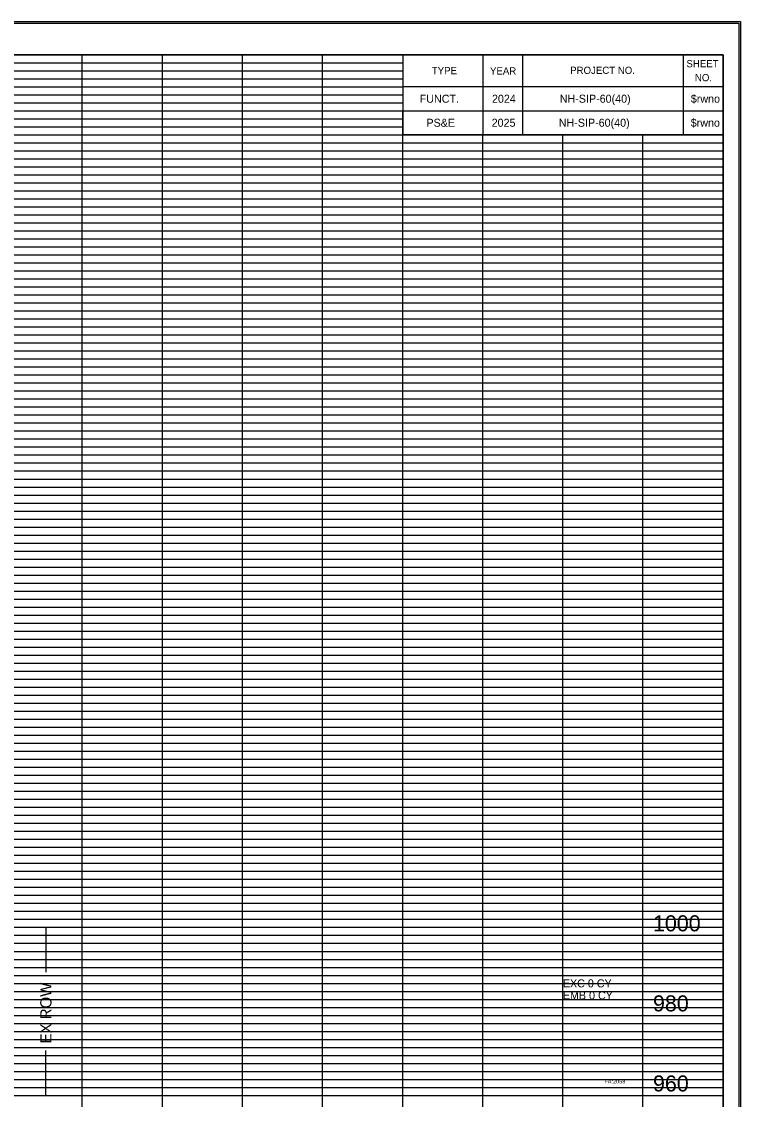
# Model space of a CAD drawing. Extents: x 2313580 to 2322968, y 282099 to 303247.
# Drawn here: x 2315763.7 to 2315943.2, y 287746.7 to 288016 of the extents above; entities that cross this region are included whole.
import ezdxf

# ---------------------------------------------------------------- set-up
doc = ezdxf.new("R2010")
doc.units = 0
for name, color, linetype in [('DESIGN - EARTHWORK - Excavation Limit Lines', 7, 'Continuous'), ('DESIGN - SCRATCH - User 1', 7, 'Continuous'), ('DESIGN - SHEET - Corner Text', 7, 'Continuous'), ('DESIGN - SHEET - Light Grid', 7, 'Continuous'), ('DESIGN - SHEET - Linework', 7, 'Continuous'), ('DESIGN - SHEET - Plot Shape', 7, 'Continuous'), ('DESIGN - TYPICAL - Text', 7, 'Continuous'), ('Prop_ CL text', 7, 'Continuous'), ('SURVEY - PROPERTY - ROW Lines Text', 7, 'Continuous')]:
    doc.layers.add(name, color=color, linetype=linetype)

msp = doc.modelspace()

# ---------------------------------------------------------------- linework, layer by layer
at = {"layer": 'DESIGN - SCRATCH - User 1'}
for p, q in [((2315868.88, 287996.67), (2315868.88, 287996.67)), ((2315883.68, 287996.67), (2315883.68, 287996.67)), ((2315908.68, 287996.67), (2315908.68, 287996.67)), ((2315933.68, 287996.67), (2315933.68, 287996.67)), ((2315868.88, 287990.67), (2315868.88, 287990.67)), ((2315883.68, 287990.67), (2315883.68, 287990.67)), ((2315908.68, 287990.67), (2315908.68, 287990.67)), ((2315933.68, 287990.67), (2315933.68, 287990.67))]:
    msp.add_line(p, q, dxfattribs=at)
at = {"layer": 'DESIGN - SHEET - Light Grid'}
for p, q in [((2315618.88, 288005.67), (2315778.88, 288005.67)), ((2315618.88, 288003.67), (2315778.88, 288003.67)), ((2315778.88, 288005.67), (2315858.88, 288005.67)), ((2315778.88, 288003.67), (2315858.88, 288003.67)), ((2315618.88, 288001.67), (2315778.88, 288001.67)), ((2315778.88, 288001.67), (2315858.88, 288001.67)), ((2315618.88, 287999.67), (2315778.88, 287999.67)), ((2315618.88, 287997.67), (2315778.88, 287997.67)), ((2315778.88, 287999.67), (2315858.88, 287999.67)), ((2315778.88, 287997.67), (2315858.88, 287997.67)), ((2315618.88, 287995.67), (2315778.88, 287995.67)), ((2315778.88, 287995.67), (2315858.88, 287995.67)), ((2315618.88, 287993.67), (2315778.88, 287993.67)), ((2315778.88, 287993.67), (2315858.88, 287993.67)), ((2315618.88, 287991.67), (2315778.88, 287991.67)), ((2315618.88, 287989.67), (2315778.88, 287989.67)), ((2315778.88, 287991.67), (2315858.88, 287991.67)), ((2315778.88, 287989.67), (2315858.88, 287989.67)), ((2315618.88, 287985.67), (2315778.88, 287985.67)), ((2315778.88, 287985.67), (2315938.88, 287985.67)), ((2315618.88, 287983.67), (2315778.88, 287983.67)), ((2315618.88, 287981.67), (2315778.88, 287981.67)), ((2315778.88, 287983.67), (2315938.88, 287983.67)), ((2315778.88, 287981.67), (2315938.88, 287981.67)), ((2315618.88, 287979.67), (2315778.88, 287979.67)), ((2315778.88, 287979.67), (2315938.88, 287979.67)), ((2315618.88, 287977.67), (2315778.88, 287977.67)), ((2315778.88, 287977.67), (2315938.88, 287977.67)), ((2315618.88, 287975.67), (2315778.88, 287975.67)), ((2315618.88, 287973.67), (2315778.88, 287973.67)), ((2315778.88, 287975.67), (2315938.88, 287975.67)), ((2315778.88, 287973.67), (2315938.88, 287973.67)), ((2315618.88, 287971.67), (2315778.88, 287971.67)), ((2315778.88, 287971.67), (2315938.88, 287971.67)), ((2315618.88, 287969.67), (2315778.88, 287969.67)), ((2315778.88, 287969.67), (2315938.88, 287969.67)), ((2315618.88, 287965.67), (2315778.88, 287965.67)), ((2315778.88, 287965.67), (2315938.88, 287965.67)), ((2315618.88, 287963.67), (2315778.88, 287963.67)), ((2315778.88, 287963.67), (2315938.88, 287963.67)), ((2315618.88, 287961.67), (2315778.88, 287961.67)), ((2315778.88, 287961.67), (2315938.88, 287961.67)), ((2315618.88, 287959.67), (2315778.88, 287959.67)), ((2315618.88, 287957.67), (2315778.88, 287957.67)), ((2315778.88, 287959.67), (2315938.88, 287959.67)), ((2315778.88, 287957.67), (2315938.88, 287957.67)), ((2315618.88, 287955.67), (2315778.88, 287955.67)), ((2315778.88, 287955.67), (2315938.88, 287955.67)), ((2315618.88, 287953.67), (2315778.88, 287953.67)), ((2315778.88, 287953.67), (2315938.88, 287953.67)), ((2315618.88, 287951.67), (2315778.88, 287951.67)), ((2315618.88, 287949.67), (2315778.88, 287949.67)), ((2315778.88, 287951.67), (2315938.88, 287951.67)), ((2315778.88, 287949.67), (2315938.88, 287949.67)), ((2315618.88, 287945.67), (2315778.88, 287945.67)), ((2315778.88, 287945.67), (2315938.88, 287945.67)), ((2315618.88, 287943.67), (2315778.88, 287943.67)), ((2315618.88, 287941.67), (2315778.88, 287941.67)), ((2315778.88, 287943.67), (2315938.88, 287943.67)), ((2315778.88, 287941.67), (2315938.88, 287941.67)), ((2315618.88, 287939.67), (2315778.88, 287939.67)), ((2315778.88, 287939.67), (2315938.88, 287939.67)), ((2315618.88, 287937.67), (2315778.88, 287937.67)), ((2315778.88, 287937.67), (2315938.88, 287937.67)), ((2315618.88, 287935.67), (2315778.88, 287935.67)), ((2315618.88, 287933.67), (2315778.88, 287933.67)), ((2315778.88, 287935.67), (2315938.88, 287935.67)), ((2315778.88, 287933.67), (2315938.88, 287933.67)), ((2315618.88, 287931.67), (2315778.88, 287931.67)), ((2315778.88, 287931.67), (2315938.88, 287931.67)), ((2315618.88, 287929.67), (2315778.88, 287929.67)), ((2315778.88, 287929.67), (2315938.88, 287929.67)), ((2315618.88, 287925.67), (2315778.88, 287925.67)), ((2315778.88, 287925.67), (2315938.88, 287925.67)), ((2315618.88, 287923.67), (2315778.88, 287923.67)), ((2315778.88, 287923.67), (2315938.88, 287923.67)), ((2315618.88, 287921.67), (2315778.88, 287921.67)), ((2315618.88, 287919.67), (2315778.88, 287919.67)), ((2315778.88, 287921.67), (2315938.88, 287921.67)), ((2315778.88, 287919.67), (2315938.88, 287919.67)), ((2315618.88, 287917.67), (2315778.88, 287917.67)), ((2315778.88, 287917.67), (2315938.88, 287917.67)), ((2315618.88, 287915.67), (2315778.88, 287915.67)), ((2315778.88, 287915.67), (2315938.88, 287915.67)), ((2315618.88, 287913.67), (2315778.88, 287913.67)), ((2315618.88, 287911.67), (2315778.88, 287911.67)), ((2315778.88, 287913.67), (2315938.88, 287913.67)), ((2315778.88, 287911.67), (2315938.88, 287911.67)), ((2315618.88, 287909.67), (2315778.88, 287909.67)), ((2315778.88, 287909.67), (2315938.88, 287909.67)), ((2315618.88, 287905.67), (2315778.88, 287905.67)), ((2315618.88, 287903.67), (2315778.88, 287903.67)), ((2315778.88, 287905.67), (2315938.88, 287905.67)), ((2315778.88, 287903.67), (2315938.88, 287903.67)), ((2315618.88, 287901.67), (2315778.88, 287901.67)), ((2315778.88, 287901.67), (2315938.88, 287901.67)), ((2315618.88, 287899.67), (2315778.88, 287899.67)), ((2315778.88, 287899.67), (2315938.88, 287899.67)), ((2315618.88, 287897.67), (2315778.88, 287897.67)), ((2315618.88, 287895.67), (2315778.88, 287895.67)), ((2315778.88, 287897.67), (2315938.88, 287897.67)), ((2315778.88, 287895.67), (2315938.88, 287895.67)), ((2315618.88, 287893.67), (2315778.88, 287893.67)), ((2315778.88, 287893.67), (2315938.88, 287893.67)), ((2315618.88, 287891.67), (2315778.88, 287891.67)), ((2315778.88, 287891.67), (2315938.88, 287891.67)), ((2315618.88, 287889.67), (2315778.88, 287889.67)), ((2315778.88, 287889.67), (2315938.88, 287889.67)), ((2315618.88, 287885.67), (2315778.88, 287885.67)), ((2315778.88, 287885.67), (2315938.88, 287885.67)), ((2315618.88, 287883.67), (2315778.88, 287883.67)), ((2315778.88, 287883.67), (2315938.88, 287883.67)), ((2315618.88, 287881.67), (2315778.88, 287881.67)), ((2315618.88, 287879.67), (2315778.88, 287879.67)), ((2315778.88, 287881.67), (2315938.88, 287881.67)), ((2315778.88, 287879.67), (2315938.88, 287879.67)), ((2315618.88, 287877.67), (2315778.88, 287877.67)), ((2315778.88, 287877.67), (2315938.88, 287877.67)), ((2315618.88, 287875.67), (2315778.88, 287875.67)), ((2315778.88, 287875.67), (2315938.88, 287875.67)), ((2315618.88, 287873.67), (2315778.88, 287873.67)), ((2315618.88, 287871.67), (2315778.88, 287871.67)), ((2315778.88, 287873.67), (2315938.88, 287873.67)), ((2315778.88, 287871.67), (2315938.88, 287871.67)), ((2315618.88, 287869.67), (2315778.88, 287869.67)), ((2315778.88, 287869.67), (2315938.88, 287869.67)), ((2315618.88, 287865.67), (2315778.88, 287865.67)), ((2315618.88, 287863.67), (2315778.88, 287863.67)), ((2315778.88, 287865.67), (2315938.88, 287865.67)), ((2315778.88, 287863.67), (2315938.88, 287863.67)), ((2315618.88, 287861.67), (2315778.88, 287861.67)), ((2315778.88, 287861.67), (2315938.88, 287861.67)), ((2315618.88, 287859.67), (2315778.88, 287859.67)), ((2315618.88, 287857.67), (2315778.88, 287857.67)), ((2315778.88, 287859.67), (2315938.88, 287859.67)), ((2315778.88, 287857.67), (2315938.88, 287857.67)), ((2315618.88, 287855.67), (2315778.88, 287855.67)), ((2315778.88, 287855.67), (2315938.88, 287855.67)), ((2315618.88, 287853.67), (2315778.88, 287853.67)), ((2315778.88, 287853.67), (2315938.88, 287853.67)), ((2315618.88, 287851.67), (2315778.88, 287851.67)), ((2315618.88, 287849.67), (2315778.88, 287849.67)), ((2315778.88, 287851.67), (2315938.88, 287851.67)), ((2315778.88, 287849.67), (2315938.88, 287849.67)), ((2315618.88, 287845.67), (2315778.88, 287845.67)), ((2315778.88, 287845.67), (2315938.88, 287845.67)), ((2315618.88, 287843.67), (2315778.88, 287843.67)), ((2315618.88, 287841.67), (2315778.88, 287841.67)), ((2315778.88, 287843.67), (2315938.88, 287843.67)), ((2315778.88, 287841.67), (2315938.88, 287841.67)), ((2315618.88, 287839.67), (2315778.88, 287839.67)), ((2315778.88, 287839.67), (2315938.88, 287839.67)), ((2315618.88, 287837.67), (2315778.88, 287837.67)), ((2315778.88, 287837.67), (2315938.88, 287837.67)), ((2315618.88, 287835.67), (2315778.88, 287835.67)), ((2315618.88, 287833.67), (2315778.88, 287833.67)), ((2315778.88, 287835.67), (2315938.88, 287835.67)), ((2315778.88, 287833.67), (2315938.88, 287833.67)), ((2315618.88, 287831.67), (2315778.88, 287831.67)), ((2315778.88, 287831.67), (2315938.88, 287831.67)), ((2315618.88, 287829.67), (2315778.88, 287829.67)), ((2315778.88, 287829.67), (2315938.88, 287829.67)), ((2315618.88, 287825.67), (2315778.88, 287825.67)), ((2315778.88, 287825.67), (2315938.88, 287825.67)), ((2315618.88, 287823.67), (2315778.88, 287823.67)), ((2315778.88, 287823.67), (2315938.88, 287823.67)), ((2315618.88, 287821.67), (2315778.88, 287821.67)), ((2315778.88, 287821.67), (2315938.88, 287821.67)), ((2315618.88, 287819.67), (2315778.88, 287819.67)), ((2315618.88, 287817.67), (2315778.88, 287817.67)), ((2315778.88, 287819.67), (2315938.88, 287819.67)), ((2315778.88, 287817.67), (2315938.88, 287817.67)), ((2315618.88, 287815.67), (2315778.88, 287815.67)), ((2315778.88, 287815.67), (2315938.88, 287815.67)), ((2315618.88, 287813.67), (2315778.88, 287813.67)), ((2315778.88, 287813.67), (2315938.88, 287813.67)), ((2315618.88, 287811.67), (2315778.88, 287811.67)), ((2315618.88, 287809.67), (2315778.88, 287809.67)), ((2315778.88, 287811.67), (2315938.88, 287811.67)), ((2315778.88, 287809.67), (2315938.88, 287809.67)), ((2315618.88, 287805.67), (2315778.88, 287805.67)), ((2315778.88, 287805.67), (2315938.88, 287805.67)), ((2315618.88, 287803.67), (2315778.88, 287803.67)), ((2315618.88, 287801.67), (2315778.88, 287801.67)), ((2315778.88, 287803.67), (2315938.88, 287803.67)), ((2315778.88, 287801.67), (2315938.88, 287801.67)), ((2315618.88, 287799.67), (2315778.88, 287799.67)), ((2315778.88, 287799.67), (2315938.88, 287799.67)), ((2315618.88, 287797.67), (2315778.88, 287797.67)), ((2315778.88, 287797.67), (2315938.88, 287797.67)), ((2315618.88, 287795.67), (2315778.88, 287795.67)), ((2315618.88, 287793.67), (2315778.88, 287793.67)), ((2315778.88, 287795.67), (2315938.88, 287795.67)), ((2315778.88, 287793.67), (2315938.88, 287793.67)), ((2315618.88, 287791.67), (2315778.88, 287791.67)), ((2315778.88, 287791.67), (2315938.88, 287791.67)), ((2315618.88, 287789.67), (2315778.88, 287789.67)), ((2315778.88, 287789.67), (2315938.88, 287789.67)), ((2315618.88, 287785.67), (2315778.88, 287785.67)), ((2315778.88, 287785.67), (2315938.88, 287785.67)), ((2315618.88, 287783.67), (2315778.88, 287783.67)), ((2315778.88, 287783.67), (2315938.88, 287783.67)), ((2315618.88, 287781.67), (2315778.88, 287781.67)), ((2315618.88, 287779.67), (2315778.88, 287779.67)), ((2315778.88, 287781.67), (2315938.88, 287781.67)), ((2315778.88, 287779.67), (2315938.88, 287779.67)), ((2315618.88, 287777.67), (2315778.88, 287777.67)), ((2315778.88, 287777.67), (2315938.88, 287777.67)), ((2315618.88, 287775.67), (2315778.88, 287775.67)), ((2315778.88, 287775.67), (2315938.88, 287775.67)), ((2315618.88, 287773.67), (2315778.88, 287773.67)), ((2315618.88, 287771.67), (2315778.88, 287771.67)), ((2315778.88, 287773.67), (2315938.88, 287773.67)), ((2315778.88, 287771.67), (2315938.88, 287771.67)), ((2315618.88, 287769.67), (2315778.88, 287769.67)), ((2315778.88, 287769.67), (2315938.88, 287769.67)), ((2315618.88, 287765.67), (2315778.88, 287765.67)), ((2315618.88, 287763.67), (2315778.88, 287763.67)), ((2315778.88, 287765.67), (2315938.88, 287765.67)), ((2315778.88, 287763.67), (2315938.88, 287763.67)), ((2315618.88, 287761.67), (2315778.88, 287761.67)), ((2315778.88, 287761.67), (2315938.88, 287761.67)), ((2315618.88, 287759.67), (2315778.88, 287759.67)), ((2315778.88, 287759.67), (2315938.88, 287759.67)), ((2315618.88, 287757.67), (2315778.88, 287757.67)), ((2315618.88, 287755.67), (2315778.88, 287755.67)), ((2315778.88, 287757.67), (2315938.88, 287757.67)), ((2315778.88, 287755.67), (2315938.88, 287755.67)), ((2315618.88, 287753.67), (2315778.88, 287753.67)), ((2315778.88, 287753.67), (2315938.88, 287753.67)), ((2315618.88, 287751.67), (2315778.88, 287751.67)), ((2315778.88, 287751.67), (2315938.88, 287751.67)), ((2315618.88, 287749.67), (2315778.88, 287749.67)), ((2315778.88, 287749.67), (2315938.88, 287749.67))]:
    msp.add_line(p, q, dxfattribs=at)
at = {"layer": 'DESIGN - SHEET - Linework'}
for p, q in [((2315262.42, 288015.95), (2315943.22, 288015.95)), ((2315943.22, 288015.95), (2315943.22, 287579.39)), ((2315778.88, 287587.67), (2315778.88, 288007.67)), ((2315798.88, 287587.67), (2315798.88, 288007.67)), ((2315818.88, 287587.67), (2315818.88, 288007.67)), ((2315838.88, 287587.67), (2315838.88, 288007.67)), ((2315298.88, 287987.67), (2315858.88, 287987.67)), ((2315858.88, 287587.67), (2315858.88, 287987.67)), ((2315878.88, 287587.67), (2315878.88, 287987.67)), ((2315898.88, 287587.67), (2315898.88, 287987.67)), ((2315918.88, 287587.67), (2315918.88, 287987.67)), ((2315298.88, 287967.67), (2315938.88, 287967.67)), ((2315298.88, 287947.67), (2315938.88, 287947.67)), ((2315298.88, 287927.67), (2315938.88, 287927.67)), ((2315298.88, 287907.67), (2315938.88, 287907.67)), ((2315298.88, 287887.67), (2315938.88, 287887.67)), ((2315298.88, 287867.67), (2315938.88, 287867.67)), ((2315298.88, 287847.67), (2315938.88, 287847.67)), ((2315298.88, 287827.67), (2315938.88, 287827.67)), ((2315298.88, 287807.67), (2315938.88, 287807.67)), ((2315298.88, 287787.67), (2315938.88, 287787.67)), ((2315298.88, 287767.67), (2315938.88, 287767.67)), ((2315298.88, 287747.67), (2315938.88, 287747.67))]:
    msp.add_line(p, q, dxfattribs=at)
for points in [[(2315298.88, 288007.67), (2315298.88, 287587.67), (2315938.88, 287587.67), (2315938.88, 288007.67), (2315298.88, 288007.67)], [(2315858.88, 288007.67), (2315858.88, 287987.67), (2315938.88, 287987.67), (2315938.88, 288007.67), (2315928.88, 288007.67), (2315928.88, 287987.67), (2315888.88, 287987.67), (2315888.88, 288007.67), (2315878.88, 288007.67), (2315878.88, 287987.67), (2315938.88, 287987.67), (2315858.88, 287987.67), (2315858.88, 287993.67), (2315938.88, 287993.67), (2315938.88, 287999.67), (2315858.88, 287999.67)]]:
    msp.add_lwpolyline(points, dxfattribs=at)
at = {"layer": 'DESIGN - SHEET - Plot Shape'}
for points in [[(2315262.82, 288015.55), (2315942.82, 288015.55), (2315942.82, 287579.79), (2315262.82, 287579.79)], [(2315281.88, 288007.67), (2315938.88, 288007.67), (2315938.88, 287582.67), (2315281.88, 287582.67)]]:
    msp.add_lwpolyline(points, close=True, dxfattribs=at)
at = {"layer": 'SURVEY - PROPERTY - ROW Lines Text'}
for p, q in [((2315769.79, 287789.67), (2315769.79, 287778.47)), ((2315769.79, 287747.67), (2315769.79, 287758.87))]:
    msp.add_line(p, q, dxfattribs=at)

# ---------------------------------------------------------------- texts
at = {"layer": 'DESIGN - EARTHWORK - Excavation Limit Lines'}
for s, p in [('EXC 0 CY', (2315898.88, 287774.67)), ('EMB 0 CY', (2315898.88, 287771.67))]:
    msp.add_text(s, height=2, dxfattribs=at).set_placement(p)
at = {"layer": 'DESIGN - SHEET - Corner Text'}
for s, height, p in [('SHEET', 1.8, (2315929.74, 288004.53)), ('TYPE', 1.8, (2315866.16, 288002.79)), ('YEAR', 1.8, (2315880.69, 288002.71)), ('PROJECT NO.', 1.8, (2315900.7, 288002.87)), ('NO.', 1.8, (2315931.85, 288001.05)), ('  FUNCT.   ', 2, (2315861.65, 287995.67))]:
    msp.add_text(s, height=height, rotation=360, dxfattribs=at).set_placement(p)
for s, p in [('2024', (2315881.18, 287995.67)), ('   NH-SIP-60(40)    ', (2315895.89, 287995.67)), ('$rwno', (2315930.83, 287995.67)), (' PS&E ', (2315864.07, 287989.67)), ('2025', (2315881.1, 287989.67)), ('   NH-SIP-60(40)    ', (2315895.64, 287989.67)), ('$rwno', (2315930.81, 287989.67))]:
    msp.add_text(s, height=2, dxfattribs=at).set_placement(p)
at = {"layer": 'DESIGN - TYPICAL - Text'}
for s, p in [('1000', (2315921.38, 287788.67)), ('980', (2315921.38, 287768.67)), ('960', (2315921.38, 287748.67))]:
    msp.add_text(s, height=4, dxfattribs=at).set_placement(p)
at = {"layer": 'Prop_ CL text'}
msp.add_text('FA:2058', height=1, dxfattribs=at).set_placement((2315909.26, 287750.67))
at = {"layer": 'SURVEY - PROPERTY - ROW Lines Text'}
msp.add_text('EX ROW', height=2.8, rotation=90, dxfattribs=at).set_placement((2315771.19, 287760.67))

doc.saveas('drawing.dxf')
